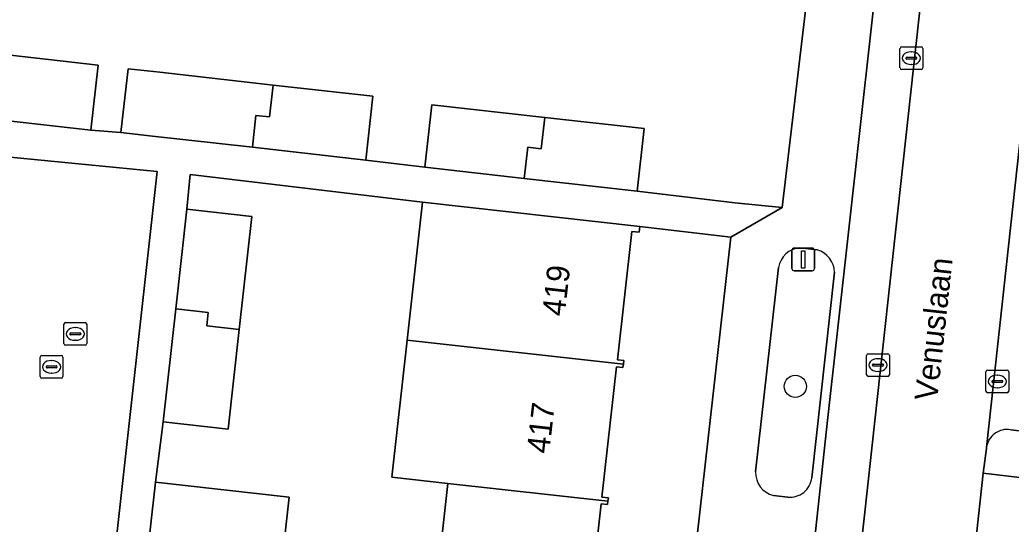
# Model space of a CAD drawing. Extents: x 161928 to 163071, y 386474 to 387428.
# Drawn here: x 162046.14 to 162089.79, y 386892.98 to 386915.21 of the extents above; entities that cross this region are included whole.
import ezdxf

# ---------------------------------------------------------------- set-up
doc = ezdxf.new("R2010")
doc.units = 0
for name, color, linetype in [('IMGEO_Boom', 7, 'Continuous'), ('IMGEO_Erf', 7, 'Continuous'), ('IMGEO_Groenvoorziening', 7, 'Continuous'), ('IMGEO_Kolk', 7, 'Continuous'), ('IMGEO_Lichtmast', 7, 'Continuous'), ('IMGEO_Openbare_ruimte_label', 7, 'Continuous'), ('IMGEO_Pand', 7, 'Continuous'), ('IMGEO_Pand_nummerreeks', 7, 'Continuous'), ('IMGEO_Parkeervlak_open', 7, 'Continuous'), ('IMGEO_Rijbaan_lokaal_open', 7, 'Continuous'), ('IMGEO_Rioolput', 7, 'Continuous'), ('IMGEO_Voetpad_open', 7, 'Continuous')]:
    doc.layers.add(name, color=color, linetype=linetype)

msp = doc.modelspace()

# ---------------------------------------------------------------- linework, layer by layer
at = {"layer": 'IMGEO_Boom'}
msp.add_circle((162080.288, 386899.055), 0.489, dxfattribs=at)
at = {"layer": 'IMGEO_Erf'}
for points in [[(162036.452, 386918.899), (162035.472, 386910.317), (162038.399, 386909.983), (162039.716, 386909.832), (162039.892, 386911.402), (162040.213, 386914.262), (162045.2, 386913.703), (162049.591, 386913.211), (162049.27, 386910.351), (162050.592, 386910.238), (162050.907, 386913.051), (162052.305, 386912.894), (162057.296, 386912.334), (162061.692, 386911.841), (162061.377, 386909.03), (162063.972, 386908.712), (162064.28, 386911.464), (162069.256, 386910.906), (162073.635, 386910.415), (162073.326, 386907.663), (162077.624, 386907.142), (162079.716, 386906.933), (162082.324, 386929.045)], [(162064.341, 386888.944), (162064.995, 386894.775), (162062.525, 386895.048), (162063.194, 386901.092), (162063.867, 386907.179), (162053.642, 386908.384), (162053.496, 386906.858), (162056.36, 386906.54), (162055.806, 386901.561), (162055.319, 386897.177), (162052.455, 386897.496), (162052.116, 386894.832), (162058.005, 386894.177), (162057.49, 386889.553)], [(162073.376, 386869.412), (162077.454, 386905.628), (162073.446, 386906.104), (162073.417, 386905.844), (162073.091, 386905.88), (162072.457, 386900.224), (162072.734, 386900.193), (162072.717, 386900.038), (162072.699, 386899.881), (162072.416, 386899.913), (162071.773, 386894.172), (162072.057, 386894.14), (162072.041, 386893.995), (162072.024, 386893.848), (162071.746, 386893.879), (162071.107, 386888.184)]]:
    msp.add_lwpolyline(points, dxfattribs=at)
at = {"layer": 'IMGEO_Groenvoorziening'}
for points in [[(162081.254, 386905.07), (162080.493, 386905.162)], [(162079.548, 386904.291), (162078.538, 386895.291)], [(162081.016, 386895.032), (162082.02, 386904.091)], [(162088.564, 386895.224), (162087.786, 386888.057), (162089.742, 386887.772), (162091.415, 386887.555), (162091.85, 386887.504), (162093.517, 386887.319), (162094.8, 386887.169)], [(162095.479, 386894.402), (162088.564, 386895.224)], [(162079.33, 386894.251), (162079.954, 386894.179)]]:
    msp.add_lwpolyline(points, dxfattribs=at)
for centre, radius, start, end in [((162080.582, 386904.118), 1.048, 94.8588, 170.4743), ((162080.931, 386904.028), 1.091, 3.3147, 72.7668), ((162079.571, 386895.256), 1.034, 178.0841, 256.4972), ((162080.06, 386895.134), 0.961, 263.6545, 353.8885)]:
    msp.add_arc(centre, radius, start, end, dxfattribs=at)
at = {"layer": 'IMGEO_Kolk'}
for p, q in [((162084.898, 386913.091), (162084.898, 386913.943)), ((162084.973, 386914.017), (162085.825, 386914.017)), ((162085.386, 386913.797), (162085.411, 386913.797)), ((162085.899, 386913.943), (162085.899, 386913.091)), ((162085.157, 386913.511), (162085.157, 386913.523)), ((162085.595, 386913.474), (162085.197, 386913.474)), ((162085.2, 386913.56), (162085.598, 386913.56)), ((162085.641, 386913.523), (162085.641, 386913.511)), ((162085.825, 386913.017), (162084.973, 386913.017)), ((162085.409, 386913.237), (162085.384, 386913.237)), ((162047.041, 386899.49), (162047.041, 386900.342)), ((162047.116, 386900.416), (162047.968, 386900.416)), ((162047.529, 386900.196), (162047.554, 386900.196)), ((162048.042, 386900.342), (162048.042, 386899.49)), ((162083.43, 386899.569), (162083.43, 386900.421)), ((162083.505, 386900.495), (162084.357, 386900.495)), ((162083.918, 386900.275), (162083.943, 386900.275)), ((162084.431, 386900.421), (162084.431, 386899.569)), ((162047.3, 386899.91), (162047.3, 386899.922)), ((162047.738, 386899.873), (162047.34, 386899.873)), ((162047.343, 386899.959), (162047.741, 386899.959)), ((162047.784, 386899.922), (162047.784, 386899.91)), ((162083.689, 386899.989), (162083.689, 386900.001)), ((162084.127, 386899.952), (162083.729, 386899.952)), ((162083.732, 386900.038), (162084.13, 386900.038)), ((162084.173, 386900.001), (162084.173, 386899.989)), ((162088.759, 386899.771), (162089.611, 386899.771)), ((162047.968, 386899.416), (162047.116, 386899.416)), ((162047.552, 386899.636), (162047.527, 386899.636)), ((162084.357, 386899.495), (162083.505, 386899.495)), ((162083.941, 386899.715), (162083.916, 386899.715)), ((162088.684, 386898.845), (162088.684, 386899.697)), ((162088.986, 386899.314), (162089.384, 386899.314)), ((162089.172, 386899.551), (162089.197, 386899.551)), ((162089.685, 386899.697), (162089.685, 386898.845)), ((162088.943, 386899.265), (162088.943, 386899.277)), ((162089.381, 386899.228), (162088.983, 386899.228)), ((162089.195, 386898.991), (162089.17, 386898.991)), ((162089.427, 386899.277), (162089.427, 386899.265)), ((162089.611, 386898.771), (162088.759, 386898.771))]:
    msp.add_line(p, q, dxfattribs=at)
for points in [[(162084.898, 386913.091), (162084.898, 386913.943)], [(162084.973, 386914.017), (162085.825, 386914.017)], [(162085.899, 386913.943), (162085.899, 386913.091)], [(162085.825, 386913.017), (162084.973, 386913.017)], [(162047.041, 386899.49), (162047.041, 386900.342)], [(162047.116, 386900.416), (162047.968, 386900.416)], [(162048.042, 386900.342), (162048.042, 386899.49)], [(162083.43, 386899.569), (162083.43, 386900.421)], [(162083.505, 386900.495), (162084.357, 386900.495)], [(162084.431, 386900.421), (162084.431, 386899.569)], [(162088.759, 386899.771), (162089.611, 386899.771)], [(162047.968, 386899.416), (162047.116, 386899.416)], [(162084.357, 386899.495), (162083.505, 386899.495)], [(162088.684, 386898.845), (162088.684, 386899.697)], [(162089.685, 386899.697), (162089.685, 386898.845)], [(162089.611, 386898.771), (162088.759, 386898.771)]]:
    msp.add_lwpolyline(points, dxfattribs=at)
for centre, radius, start, end in [((162084.975, 386913.941), 0.0765, 91.552, 178.448), ((162084.975, 386913.941), 0.0765, 91.552, 178.448), ((162085.823, 386913.941), 0.0765, 1.552, 88.448), ((162085.823, 386913.941), 0.0765, 1.552, 88.448), ((162085.197, 386913.52), 0.0403, 85.8775, 175.7526), ((162085.194, 386913.51), 0.0366, 178.938, 274.7102), ((162085.598, 386913.517), 0.043, 264.8664, 352.4533), ((162085.602, 386913.522), 0.0386, 1.7309, 96.639), ((162084.975, 386913.093), 0.0765, 181.552, 268.448), ((162084.975, 386913.093), 0.0765, 181.552, 268.448), ((162085.823, 386913.093), 0.0765, 271.552, 358.448), ((162085.823, 386913.093), 0.0765, 271.552, 358.448), ((162047.118, 386900.34), 0.0765, 91.552, 178.448), ((162047.118, 386900.34), 0.0765, 91.552, 178.448), ((162047.966, 386900.34), 0.0765, 1.552, 88.448), ((162047.966, 386900.34), 0.0765, 1.552, 88.448), ((162083.507, 386900.419), 0.0765, 91.552, 178.448), ((162083.507, 386900.419), 0.0765, 91.552, 178.448), ((162084.355, 386900.419), 0.0765, 1.552, 88.448), ((162084.355, 386900.419), 0.0765, 1.552, 88.448), ((162047.34, 386899.919), 0.0403, 85.8775, 175.7526), ((162047.337, 386899.909), 0.0366, 178.938, 274.7102), ((162047.741, 386899.916), 0.043, 264.8664, 352.4533), ((162047.745, 386899.921), 0.0386, 1.7309, 96.639), ((162083.729, 386899.998), 0.0403, 85.8775, 175.7526), ((162083.726, 386899.988), 0.0366, 178.938, 274.7102), ((162084.13, 386899.995), 0.043, 264.8664, 352.4533), ((162084.134, 386900), 0.0386, 1.7309, 96.639), ((162088.761, 386899.695), 0.0765, 91.552, 178.448), ((162088.761, 386899.695), 0.0765, 91.552, 178.448), ((162089.609, 386899.695), 0.0765, 1.552, 88.448), ((162089.609, 386899.695), 0.0765, 1.552, 88.448), ((162047.118, 386899.492), 0.0765, 181.552, 268.448), ((162047.118, 386899.492), 0.0765, 181.552, 268.448), ((162047.966, 386899.492), 0.0765, 271.552, 358.448), ((162047.966, 386899.492), 0.0765, 271.552, 358.448), ((162083.507, 386899.571), 0.0765, 181.552, 268.448), ((162083.507, 386899.571), 0.0765, 181.552, 268.448), ((162084.355, 386899.571), 0.0765, 271.552, 358.448), ((162084.355, 386899.571), 0.0765, 271.552, 358.448), ((162088.983, 386899.274), 0.0403, 85.8775, 175.7526), ((162089.388, 386899.276), 0.0386, 1.7309, 96.639), ((162088.98, 386899.264), 0.0366, 178.938, 274.7102), ((162089.384, 386899.271), 0.043, 264.8664, 352.4533), ((162088.761, 386898.847), 0.0765, 181.552, 268.448), ((162088.761, 386898.847), 0.0765, 181.552, 268.448), ((162089.609, 386898.847), 0.0765, 271.552, 358.448), ((162089.609, 386898.847), 0.0765, 271.552, 358.448)]:
    msp.add_arc(centre, radius, start, end, dxfattribs=at)
for centre, major_axis, ratio, start_param, end_param in [((162085.385, 386913.517), (-0.387, 0.002), 0.722429, 4.712389, 7.853982), ((162085.41, 386913.517), (-0.39, 0.002), 0.717154, 1.570796, 4.712389), ((162047.528, 386899.916), (-0.387, 0.002), 0.722429, 4.712389, 7.853982), ((162047.553, 386899.916), (-0.39, 0.002), 0.717154, 1.570796, 4.712389), ((162083.917, 386899.995), (-0.387, 0.002), 0.722429, 4.712389, 7.853982), ((162083.942, 386899.995), (-0.39, 0.002), 0.717154, 1.570796, 4.712389), ((162089.171, 386899.271), (-0.387, 0.002), 0.722429, 4.712389, 7.853982), ((162089.196, 386899.271), (-0.39, 0.002), 0.717154, 1.570796, 4.712389)]:
    msp.add_ellipse(centre, major_axis=major_axis, ratio=ratio, start_param=start_param, end_param=end_param, dxfattribs=at)
at = {"layer": 'IMGEO_Lichtmast'}
for p, q in [((162080.141, 386904.246), (162080.141, 386905.046)), ((162080.141, 386905.046), (162080.141, 386904.246)), ((162080.241, 386905.146), (162081.031, 386905.146)), ((162081.031, 386905.146), (162080.241, 386905.146)), ((162081.131, 386905.046), (162081.131, 386904.246)), ((162081.131, 386904.246), (162081.131, 386905.046)), ((162081.031, 386904.146), (162080.241, 386904.146)), ((162080.241, 386904.146), (162081.031, 386904.146))]:
    msp.add_line(p, q, dxfattribs=at)
msp.add_lwpolyline([(162080.561, 386905.021), (162080.711, 386905.021), (162080.711, 386904.271), (162080.561, 386904.271), (162080.561, 386905.021)], dxfattribs=at)
for centre, start, end in [((162080.241, 386905.046), 90, 180), ((162080.241, 386905.046), 90, 180), ((162081.031, 386905.046), 0, 90), ((162081.031, 386905.046), 360, 90), ((162080.241, 386904.246), 180, 270), ((162080.241, 386904.246), 180, 270), ((162081.031, 386904.246), 270, 0), ((162081.031, 386904.246), 270, 0)]:
    msp.add_arc(centre, 0.1, start, end, dxfattribs=at)
at = {"layer": 'IMGEO_Pand'}
for points in [[(162049.591, 386913.211), (162045.2, 386913.703), (162045.04, 386912.271), (162044.443, 386912.338), (162044.283, 386910.91), (162044.582, 386910.876), (162049.27, 386910.351)], [(162057.296, 386912.334), (162052.305, 386912.894), (162050.907, 386913.051), (162050.592, 386910.238), (162051.99, 386910.082), (162056.384, 386909.59), (162056.541, 386910.994), (162057.138, 386910.927)], [(162056.384, 386909.59), (162061.377, 386909.03), (162061.692, 386911.841), (162057.296, 386912.334), (162057.138, 386910.927), (162056.541, 386910.994)], [(162068.505, 386909.596), (162069.102, 386909.529), (162069.256, 386910.906), (162064.28, 386911.464), (162063.972, 386908.712), (162068.351, 386908.221)], [(162068.351, 386908.221), (162073.326, 386907.663), (162073.635, 386910.415), (162069.256, 386910.906), (162069.102, 386909.529), (162068.505, 386909.596)], [(162072.717, 386900.038), (162072.734, 386900.193), (162072.457, 386900.224), (162073.091, 386905.88), (162073.417, 386905.844), (162073.446, 386906.104), (162063.867, 386907.179), (162063.194, 386901.092)], [(162053.009, 386902.476), (162054.441, 386902.317), (162054.375, 386901.72), (162055.806, 386901.561), (162056.36, 386906.54), (162053.496, 386906.858)], [(162052.455, 386897.496), (162055.319, 386897.177), (162055.806, 386901.561), (162054.375, 386901.72), (162054.441, 386902.317), (162053.009, 386902.476)], [(162072.416, 386899.913), (162072.699, 386899.881), (162072.717, 386900.038), (162063.194, 386901.092), (162062.525, 386895.048), (162064.995, 386894.775), (162072.041, 386893.995), (162072.057, 386894.14), (162071.773, 386894.172)], [(162051.634, 386890.502), (162053.061, 386890.345), (162052.994, 386889.749), (162054.417, 386889.592), (162054.45, 386889.891), (162057.49, 386889.553), (162058.005, 386894.177), (162052.116, 386894.832)], [(162071.746, 386893.879), (162072.024, 386893.848), (162072.041, 386893.995), (162064.995, 386894.775), (162064.341, 386888.944), (162064.055, 386888.976), (162064.036, 386888.809), (162071.359, 386887.998), (162071.376, 386888.154), (162071.107, 386888.184)]]:
    msp.add_lwpolyline(points, close=True, dxfattribs=at)
at = {"layer": 'IMGEO_Parkeervlak_open'}
for points in [[(162092.691, 386932.799), (162088.711, 386896.367)], [(162080.519, 386868.055), (162081.119, 386873.495), (162083.328, 386893.374), (162087.202, 386928.662)], [(162085.114, 386928.126), (162081.656, 386897.155), (162079.116, 386873.581), (162078.608, 386869.048)], [(162089.766, 386897.146), (162094.932, 386896.566)]]:
    msp.add_lwpolyline(points, dxfattribs=at)
msp.add_arc((162089.62, 386896.239), 0.918, 80.8759, 172.0076, dxfattribs=at)
at = {"layer": 'IMGEO_Rijbaan_lokaal_open'}
for points in [[(162093.422, 386939.204), (162088.34, 386939.739), (162087.775, 386933.809), (162087.202, 386928.662), (162083.328, 386893.374), (162081.119, 386873.495), (162080.519, 386868.055), (162080.511, 386867.872), (162079.983, 386862.893), (162079.639, 386859.749)], [(162084.603, 386859.23), (162086.247, 386874.125), (162086.574, 386877.16), (162086.715, 386878.398), (162086.915, 386879.984), (162086.926, 386880.164), (162087.574, 386886.163), (162087.786, 386888.057), (162088.564, 386895.224), (162088.706, 386896.314), (162088.711, 386896.367), (162092.691, 386932.799)], [(162052.188, 386908.526), (162044.948, 386909.235), (162044.59, 386906.099), (162044.231, 386902.963), (162043.873, 386899.828), (162043.515, 386896.692), (162043.156, 386893.556), (162042.798, 386890.42), (162042.44, 386887.285), (162042.082, 386884.149), (162041.723, 386881.013), (162041.365, 386877.877), (162041.007, 386874.742), (162040.648, 386871.606), (162040.29, 386868.47), (162051.445, 386867.107), (162070.201, 386864.995), (162071.98, 386864.795), (162072.306, 386867.789), (162070.497, 386867.994), (162051.991, 386870.069), (162050.693, 386870.214)], [(162048.13, 386872.928), (162048.97, 386879.58), (162052.188, 386908.526)]]:
    msp.add_lwpolyline(points, dxfattribs=at)
at = {"layer": 'IMGEO_Rioolput'}
for p, q in [((162048.086, 386900.942), (162048.086, 386901.794)), ((162048.161, 386901.868), (162049.013, 386901.868)), ((162048.574, 386901.648), (162048.599, 386901.648)), ((162049.087, 386901.794), (162049.087, 386900.942)), ((162048.345, 386901.362), (162048.345, 386901.374)), ((162048.783, 386901.325), (162048.385, 386901.325)), ((162048.388, 386901.411), (162048.786, 386901.411)), ((162048.597, 386901.088), (162048.572, 386901.088)), ((162048.829, 386901.374), (162048.829, 386901.362)), ((162049.013, 386900.868), (162048.161, 386900.868))]:
    msp.add_line(p, q, dxfattribs=at)
for points in [[(162048.086, 386900.942), (162048.086, 386901.794)], [(162048.161, 386901.868), (162049.013, 386901.868)], [(162049.087, 386901.794), (162049.087, 386900.942)], [(162049.013, 386900.868), (162048.161, 386900.868)]]:
    msp.add_lwpolyline(points, dxfattribs=at)
for centre, radius, start, end in [((162048.163, 386901.792), 0.0765, 91.552, 178.448), ((162048.163, 386901.792), 0.0765, 91.552, 178.448), ((162049.011, 386901.792), 0.0765, 1.552, 88.448), ((162049.011, 386901.792), 0.0765, 1.552, 88.448), ((162048.385, 386901.371), 0.0403, 85.8775, 175.7526), ((162048.382, 386901.361), 0.0366, 178.938, 274.7102), ((162048.786, 386901.368), 0.043, 264.8664, 352.4533), ((162048.79, 386901.373), 0.0386, 1.7309, 96.639), ((162048.163, 386900.944), 0.0765, 181.552, 268.448), ((162048.163, 386900.944), 0.0765, 181.552, 268.448), ((162049.011, 386900.944), 0.0765, 271.552, 358.448), ((162049.011, 386900.944), 0.0765, 271.552, 358.448)]:
    msp.add_arc(centre, radius, start, end, dxfattribs=at)
for centre, major_axis, ratio, start_param, end_param in [((162048.573, 386901.368), (-0.387, 0.002), 0.722429, 4.712389, 7.853982), ((162048.598, 386901.368), (-0.39, 0.002), 0.717154, 1.570796, 4.712389)]:
    msp.add_ellipse(centre, major_axis=major_axis, ratio=ratio, start_param=start_param, end_param=end_param, dxfattribs=at)
at = {"layer": 'IMGEO_Voetpad_open'}
for points in [[(162082.324, 386929.045), (162079.716, 386906.933), (162077.454, 386905.628), (162073.376, 386869.412), (162072.637, 386863.4), (162074.116, 386863.024)], [(162078.608, 386869.048), (162079.116, 386873.581), (162081.656, 386897.155), (162085.114, 386928.126)], [(162051.634, 386890.502), (162052.116, 386894.832), (162052.455, 386897.496), (162053.009, 386902.476), (162053.496, 386906.858), (162053.642, 386908.384), (162063.867, 386907.179), (162073.446, 386906.104), (162077.454, 386905.628), (162079.716, 386906.933), (162077.624, 386907.142), (162073.326, 386907.663), (162068.351, 386908.221), (162063.972, 386908.712), (162061.377, 386909.03), (162056.384, 386909.59), (162051.99, 386910.082), (162050.592, 386910.238), (162049.27, 386910.351), (162044.582, 386910.876)], [(162044.948, 386909.235), (162052.188, 386908.526), (162048.97, 386879.58), (162048.13, 386872.928)], [(162080.493, 386905.162), (162081.254, 386905.07)], [(162078.538, 386895.291), (162079.548, 386904.291)], [(162082.02, 386904.091), (162081.016, 386895.032)], [(162094.932, 386896.566), (162089.766, 386897.146)], [(162088.711, 386896.367), (162088.706, 386896.314), (162088.564, 386895.224), (162095.479, 386894.402)], [(162079.954, 386894.179), (162079.33, 386894.251)]]:
    msp.add_lwpolyline(points, dxfattribs=at)
for centre, radius, start, end in [((162080.582, 386904.118), 1.048, 94.8588, 170.4743), ((162080.931, 386904.028), 1.091, 3.3147, 72.7668), ((162089.62, 386896.239), 0.918, 80.8759, 172.0076), ((162079.571, 386895.256), 1.034, 178.0841, 256.4972), ((162080.06, 386895.134), 0.961, 263.6545, 353.8885)]:
    msp.add_arc(centre, radius, start, end, dxfattribs=at)

# ---------------------------------------------------------------- texts
at = {"layer": 'IMGEO_Openbare_ruimte_label'}
msp.add_text('Venuslaan', height=1, rotation=83.7421, dxfattribs=at).set_placement((162086.53, 386898.387))
at = {"layer": 'IMGEO_Pand_nummerreeks'}
for s, rotation, p in [('419', 83.5778, (162070.131, 386902.117)), ('417', 83.5774, (162069.451, 386896.064))]:
    msp.add_text(s, height=1, rotation=rotation, dxfattribs=at).set_placement(p)

doc.saveas('drawing.dxf')
